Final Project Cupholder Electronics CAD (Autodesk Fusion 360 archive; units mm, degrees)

design "NEW EIP Cupholder PCB"
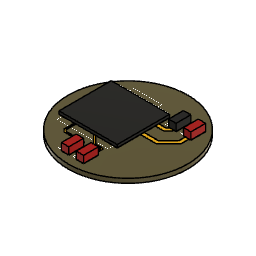
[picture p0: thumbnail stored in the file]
sketch "Outline" plane through (0, 0, 0) normal (0, 0, 1) x axis (1, 0, 0)
  circle C1 centre (0, 0) radius 20.5
canvas "Canvas1" bodies "Board"
canvas "Canvas2" bodies "Board"
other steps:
pcbextrude "PCBExtrude1"
extrude "Extrude1" sketch "Outline" blind 1.5 bodies "Board"
pcbextrude "PCBExtrude1"
box_primitive "BoxPrimitive1" DistanceX 2.54 DistanceY 5.08 DistanceZ 2.4419 OffsetDistanceX 0 OffsetDistanceY 0
pcbextrude "PCBExtrude1"
box_primitive "BoxPrimitive1" DistanceX 20 DistanceY 17.95 DistanceZ 1 OffsetDistanceX 0 OffsetDistanceY 0
pcbextrude "PCBExtrude"
create_component "CreateComponent1"
create_component "CreateComponent2"
create_component "CreateComponent3"
create_component "CreateComponent4"
create_component "CreateComponent1"
as_built_joint "As-built1"
create_component "CreateComponent3"
named bodies: "Board"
